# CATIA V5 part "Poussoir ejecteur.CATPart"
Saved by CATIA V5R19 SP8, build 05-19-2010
Part number: Poussoir éjecteur
Bounding box of the stored display mesh (mm): x -1.439 to 1.439, y 0 to 39, z -1.439 to 1.439
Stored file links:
  C:\Users\Arthur\Desktop\Catia parts\GLOCK\Ensemble culasse\Poussoir ejecteur.CATPart
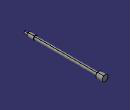
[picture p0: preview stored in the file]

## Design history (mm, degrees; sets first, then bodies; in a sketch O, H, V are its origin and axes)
Set1
  Sketch1 on yz-plane, origin (0, 0, 0), H (0, 1, 0), V (0, 0, 1)
    line L1 (2, 0.5) -> (2, 1)
    line L2 (2, 0.5) -> (0, 0.5)
    line L3 (2, 1) -> (5, 1)
    line L4 (5, 1) -> (5, 0.8)
    line L5 (5, 0.8) -> (36, 0.8)
    line L6 (36, 0.8) -> (36, 1.5)
    line L7 (36, 1.5) -> (39, 1.5)
    line L8 (39, 0) -> (39, 1.5)
    point P9 (39, 0)
    axis line L9 (-30, 0) -> (200, 0)
    point P10 (-30, 0)
    line L10 (0, 0.5) -> (0, 0)
    length L3 = 3
    length L7 = 3
    length L2 = 2
    distance L3 L9 = 1
    distance L2 L9 = 0.5
    distance L7 L9 = 1.5
    distance L8 L10 = 39
    distance L9 L5 = 0.8
    vertical: L1 V, L4 V, L6 V, L8 V, L10 V
    horizontal: L2 H, L3 H, L5 H, L7 H, L9 H
    coincidence: P10 H, P9 L9, L9 H, L10 V
Body1 (main body)
  Shaft1: profile Sketch1, axis Sketch1.L9, angle 360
